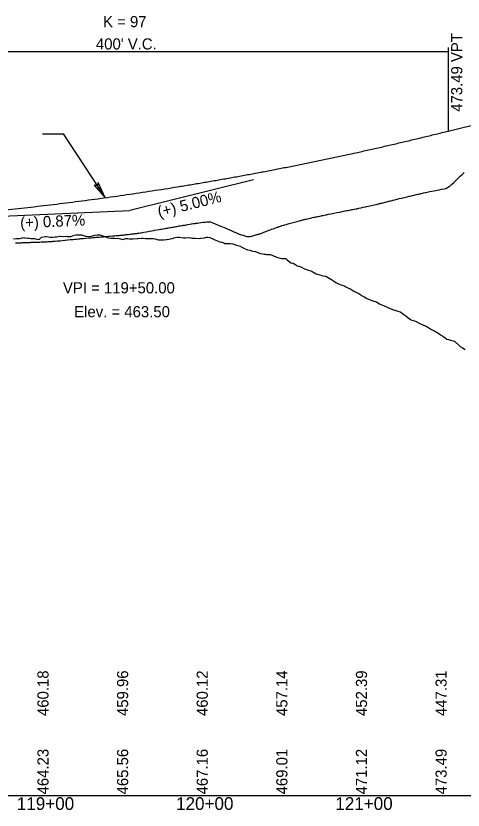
# Model space of a CAD drawing. Extents: x 2017200 to 2047700, y 854850 to 893350.
# Drawn here: x 2023378.5 to 2023659.3, y 862090.9 to 862589.8 of the extents above; entities that cross this region are included whole.
import ezdxf

# ---------------------------------------------------------------- set-up
doc = ezdxf.new("R2010")
doc.units = 0
for name, color, linetype in [('RD_DDB_GradeTX', 7, 'Continuous'), ('RD_DDB_Profile_Elev', 7, 'Continuous'), ('RD_DDB_Profile_EX', 7, 'Continuous'), ('RD_DDB_Profile_Lbl', 7, 'Continuous'), ('RD_DDB_Profile_PR', 7, 'Continuous'), ('RD_DDB_StaTX', 7, 'Continuous'), ('RD_DDB_StripGrade', 7, 'Continuous'), ('RD_DDB_VCLbl', 7, 'Continuous'), ('RD_GPK_Profile_Cell', 7, 'Continuous')]:
    doc.layers.add(name, color=color, linetype=linetype)

msp = doc.modelspace()

# ---------------------------------------------------------------- linework, layer by layer
at = {"layer": 'RD_DDB_GradeTX'}
for p in [(2023527.61, 862486.89), (2023370.08, 862464.03)]:
    msp.add_line(p, (2023450, 862467.5), dxfattribs=at)
at = {"layer": 'RD_DDB_Profile_Elev'}
msp.add_lwpolyline([(2023378.28, 862447.19), (2023378.98, 862447.22), (2023379.7, 862447.25), (2023380.47, 862447.28), (2023381.27, 862447.31), (2023381.93, 862447.33), (2023382.5, 862447.36), (2023383.29, 862447.39), (2023383.72, 862447.4), (2023384.48, 862447.43), (2023384.92, 862447.45), (2023385.5, 862447.47), (2023386.21, 862447.5), (2023386.92, 862447.52), (2023387.55, 862447.54), (2023388.07, 862447.57), (2023388.88, 862447.59), (2023389.28, 862447.61), (2023389.71, 862447.63), (2023390.57, 862447.66), (2023391.11, 862447.68), (2023392.03, 862447.71), (2023392.67, 862447.74), (2023393.6, 862447.77), (2023394.29, 862447.81), (2023395.18, 862447.84), (2023395.9, 862447.87), (2023396.94, 862447.91), (2023397.43, 862447.94), (2023398.13, 862447.97), (2023398.8, 862448), (2023399.34, 862448.03), (2023399.89, 862448.07), (2023400.56, 862448.11), (2023401.24, 862448.17), (2023401.75, 862448.2), (2023402.67, 862448.28), (2023403.07, 862448.31), (2023404.7, 862448.46), (2023405.89, 862448.58), (2023406.22, 862448.61), (2023407.85, 862448.78), (2023409.17, 862448.91), (2023409.51, 862448.94), (2023410.81, 862449.08), (2023411.12, 862449.11), (2023411.42, 862449.14), (2023412.57, 862449.26), (2023413.8, 862449.38), (2023414.56, 862449.45), (2023415.48, 862449.54), (2023416.59, 862449.64), (2023417.87, 862449.76), (2023418.66, 862449.84), (2023419.29, 862449.89), (2023420.46, 862450), (2023420.83, 862450.03), (2023422.42, 862450.18), (2023424, 862450.32), (2023425.46, 862450.45), (2023425.89, 862450.48), (2023426.8, 862450.56), (2023427.98, 862450.66), (2023428.72, 862450.72), (2023429.72, 862450.81), (2023430.71, 862450.89), (2023431.85, 862450.98), (2023432.18, 862451.01), (2023433.42, 862451.1), (2023433.78, 862451.13), (2023435.05, 862451.23), (2023435.44, 862451.26), (2023435.8, 862451.29), (2023436.75, 862451.37), (2023437.07, 862451.39), (2023437.39, 862451.42), (2023439.12, 862451.56), (2023440.58, 862451.68), (2023441.5, 862451.76), (2023441.98, 862451.8), (2023442.72, 862451.87), (2023443.29, 862451.92), (2023443.99, 862451.99), (2023444.32, 862452.03), (2023444.98, 862452.09), (2023445.6, 862452.17), (2023446.32, 862452.24), (2023447.03, 862452.33), (2023447.8, 862452.4), (2023448.54, 862452.49), (2023449.31, 862452.57), (2023450.05, 862452.66), (2023450.79, 862452.74), (2023451.48, 862452.83), (2023452.14, 862452.9), (2023452.76, 862452.98), (2023453.28, 862453.04), (2023453.85, 862453.12), (2023454.38, 862453.19), (2023454.85, 862453.27), (2023455.18, 862453.32), (2023455.6, 862453.38), (2023456.63, 862453.55), (2023457.17, 862453.63), (2023458.83, 862453.91), (2023460.44, 862454.19), (2023462.14, 862454.5), (2023463.85, 862454.79), (2023465.02, 862455), (2023465.7, 862455.12), (2023467.04, 862455.35), (2023468.17, 862455.55), (2023469.32, 862455.76), (2023469.96, 862455.87), (2023470.88, 862456.04), (2023471.25, 862456.1), (2023472.3, 862456.29), (2023472.94, 862456.4), (2023473.82, 862456.56), (2023474.29, 862456.64), (2023475.35, 862456.83), (2023475.8, 862456.9), (2023476.14, 862456.96), (2023476.56, 862457.03), (2023477.14, 862457.13), (2023477.5, 862457.2), (2023478.38, 862457.35), (2023478.9, 862457.44), (2023479.57, 862457.56), (2023480.31, 862457.69), (2023481.12, 862457.83), (2023481.72, 862457.93), (2023482.66, 862458.1), (2023483.1, 862458.17), (2023483.41, 862458.23), (2023483.8, 862458.29), (2023484.44, 862458.41), (2023484.75, 862458.45), (2023485.83, 862458.64), (2023486.2, 862458.7), (2023487.66, 862458.94), (2023488.65, 862459.11), (2023488.97, 862459.16), (2023489.8, 862459.3), (2023490.64, 862459.43), (2023491.03, 862459.49), (2023491.35, 862459.54), (2023492.45, 862459.69), (2023493.6, 862459.85), (2023494.9, 862460.02), (2023496.2, 862460.18), (2023497.37, 862460.33), (2023498.32, 862460.44), (2023500.77, 862460.35), (2023501.14, 862460.2), (2023502.09, 862459.81), (2023503.58, 862459.19), (2023505.07, 862458.57), (2023505.51, 862458.39), (2023506.61, 862457.93), (2023507.27, 862457.65), (2023508.2, 862457.27), (2023509.23, 862456.84), (2023509.85, 862456.58), (2023511.26, 862455.99), (2023511.57, 862455.86), (2023512.75, 862455.37), (2023513.62, 862455), (2023515.34, 862454.26), (2023516.63, 862453.7), (2023517.13, 862453.49), (2023518.02, 862453.1), (2023518.73, 862452.8), (2023519.58, 862452.46), (2023519.98, 862452.28), (2023521.17, 862452.06), (2023522.18, 862451.74), (2023522.74, 862451.42), (2023523.79, 862451.15), (2023524.82, 862451.13), (2023525.63, 862451.29), (2023526.14, 862451.41), (2023526.59, 862451.54), (2023527.27, 862451.72), (2023527.99, 862451.9), (2023528.54, 862452.06), (2023529.22, 862452.25), (2023529.78, 862452.41), (2023530.36, 862452.57), (2023530.84, 862452.73), (2023531.28, 862452.88), (2023531.72, 862453), (2023532.9, 862453.42), (2023534.14, 862453.9), (2023534.46, 862454.02), (2023535.8, 862454.53), (2023537.04, 862455), (2023537.42, 862455.14), (2023538.08, 862455.39), (2023539.3, 862455.84), (2023540.66, 862456.34), (2023541.03, 862456.48), (2023541.7, 862456.72), (2023542.1, 862456.87), (2023542.52, 862457.01), (2023542.89, 862457.13), (2023543.69, 862457.42), (2023544.12, 862457.55), (2023544.69, 862457.75), (2023545.34, 862457.94), (2023545.69, 862458.06), (2023546.58, 862458.32), (2023546.89, 862458.41), (2023547.25, 862458.51), (2023548.35, 862458.83), (2023548.94, 862459), (2023550.2, 862459.36), (2023551.78, 862459.8), (2023552.55, 862460.02), (2023553.41, 862460.26), (2023555.1, 862460.73), (2023556.47, 862461.11), (2023557.36, 862461.34), (2023557.69, 862461.42), (2023558.32, 862461.59), (2023558.9, 862461.73), (2023559.39, 862461.85), (2023559.79, 862461.94), (2023560.12, 862462.02), (2023560.77, 862462.17), (2023561.57, 862462.35), (2023562.38, 862462.53), (2023563.41, 862462.77), (2023564.11, 862462.92), (2023564.8, 862463.08), (2023565.86, 862463.31), (2023566.44, 862463.43), (2023567.03, 862463.56), (2023567.54, 862463.67), (2023567.98, 862463.77), (2023569.05, 862463.99), (2023569.36, 862464.06), (2023570.31, 862464.26), (2023570.65, 862464.34), (2023571.25, 862464.46), (2023572.15, 862464.65), (2023573.3, 862464.89), (2023573.8, 862465), (2023574.27, 862465.1), (2023574.76, 862465.2), (2023576.39, 862465.53), (2023578.2, 862465.9), (2023580.06, 862466.28), (2023581.72, 862466.61), (2023582.78, 862466.81), (2023583.32, 862466.92), (2023584.18, 862467.09), (2023585.12, 862467.27), (2023585.51, 862467.34), (2023586.28, 862467.49), (2023586.74, 862467.58), (2023587.17, 862467.66), (2023588.02, 862467.82), (2023588.74, 862467.96), (2023589.44, 862468.09), (2023589.98, 862468.2), (2023590.86, 862468.36), (2023591.38, 862468.46), (2023592.36, 862468.65), (2023592.81, 862468.74), (2023593.24, 862468.82), (2023593.91, 862468.97), (2023595.19, 862469.25), (2023595.98, 862469.43), (2023596.61, 862469.56), (2023598.15, 862469.92), (2023598.5, 862470), (2023599.89, 862470.31), (2023601.71, 862470.71), (2023603.38, 862471.08), (2023604.58, 862471.34), (2023604.97, 862471.44), (2023605.94, 862471.66), (2023606.48, 862471.8), (2023606.84, 862471.88), (2023607.22, 862471.96), (2023607.71, 862472.08), (2023608.43, 862472.26), (2023608.87, 862472.37), (2023609.75, 862472.6), (2023610.46, 862472.78), (2023610.8, 862472.87), (2023611.81, 862473.13), (2023612.31, 862473.26), (2023613.4, 862473.54), (2023614.07, 862473.72), (2023614.9, 862473.93), (2023615.21, 862474.01), (2023616.41, 862474.31), (2023617.18, 862474.5), (2023617.69, 862474.63), (2023618.11, 862474.73), (2023619.28, 862475.02), (2023620.79, 862475.4), (2023621.31, 862475.53), (2023622.49, 862475.81), (2023624.16, 862476.21), (2023624.93, 862476.4), (2023625.41, 862476.51), (2023625.85, 862476.61), (2023626.93, 862476.87), (2023627.53, 862477.01), (2023628.55, 862477.25), (2023629.18, 862477.39), (2023629.89, 862477.56), (2023630.79, 862477.76), (2023631.31, 862477.88), (2023632.32, 862478.11), (2023632.66, 862478.18), (2023633, 862478.25), (2023634.04, 862478.49), (2023634.44, 862478.57), (2023635.46, 862478.8), (2023635.84, 862478.88), (2023636.73, 862479.07), (2023637.7, 862479.28), (2023638.47, 862479.44), (2023639.73, 862479.71), (2023641.16, 862480), (2023643.03, 862480.37), (2023644.32, 862480.62), (2023645.81, 862480.91), (2023647.36, 862481.22), (2023648.38, 862481.41), (2023650.66, 862482.55), (2023651.02, 862482.89), (2023651.77, 862483.61), (2023652.08, 862483.89), (2023653.43, 862485.17), (2023653.88, 862485.61), (2023654.93, 862486.6), (2023655.75, 862487.39), (2023656.63, 862488.22), (2023657.5, 862489.06), (2023658.49, 862490), (2023660.06, 862491.51)], dxfattribs=at)
at = {"layer": 'RD_DDB_Profile_EX'}
msp.add_lwpolyline([(2023376.92, 862449.71), (2023378.85, 862450.02), (2023380.22, 862449.95), (2023381.03, 862450.06), (2023382.47, 862450.34), (2023382.82, 862450.41), (2023383.51, 862450.59), (2023384.07, 862450.5), (2023386.09, 862450.23), (2023386.8, 862450.14), (2023387.84, 862450.08), (2023389.71, 862449.97), (2023390.16, 862449.93), (2023392.38, 862449.44), (2023393.37, 862449.62), (2023394.66, 862450.73), (2023396.94, 862451.27), (2023397.58, 862451.19), (2023399.92, 862450.91), (2023400.56, 862450.84), (2023401.49, 862450.74), (2023403.2, 862451.01), (2023403.77, 862451.07), (2023404.18, 862451.12), (2023405.07, 862451.22), (2023406.05, 862451.36), (2023406.47, 862451.4), (2023407.8, 862451.33), (2023409.74, 862451.4), (2023410.61, 862451.3), (2023411.42, 862451.28), (2023413, 862451.27), (2023415.18, 862451.98), (2023416.27, 862452.34), (2023418.96, 862452.31), (2023419.76, 862452.3), (2023420.3, 862452.09), (2023422.28, 862451.4), (2023422.78, 862451.35), (2023424.59, 862451.31), (2023426.04, 862451.4), (2023428.04, 862451.97), (2023429.51, 862452.34), (2023431.22, 862452.18), (2023432.54, 862451.8), (2023433.13, 862451.57), (2023435.87, 862450.54), (2023436.75, 862450.43), (2023438.11, 862450.27), (2023439.03, 862450.18), (2023440.41, 862450.09), (2023442.27, 862449.96), (2023442.71, 862450.11), (2023443.99, 862449.75), (2023445.02, 862449.55), (2023445.51, 862449.44), (2023447.61, 862450.04), (2023448.75, 862449.95), (2023449.63, 862449.79), (2023451.23, 862449.78), (2023452.09, 862449.79), (2023454.85, 862449.92), (2023455.21, 862449.94), (2023457.46, 862450.12), (2023458.46, 862450.18), (2023459.93, 862450.08), (2023461.18, 862449.98), (2023461.67, 862450.01), (2023462.08, 862450.02), (2023462.8, 862450.03), (2023464.89, 862450), (2023465.7, 862449.77), (2023468.15, 862449.1), (2023469.32, 862449.09), (2023470.44, 862449.07), (2023471.33, 862449.23), (2023472.94, 862449.4), (2023473.34, 862449.44), (2023474.55, 862449.5), (2023476.56, 862450.03), (2023477.4, 862450.23), (2023477.76, 862450.36), (2023479.73, 862450.89), (2023480.18, 862450.88), (2023480.97, 862450.85), (2023483.8, 862450.5), (2023484.38, 862450.35), (2023484.92, 862450.46), (2023487.42, 862450.7), (2023489.04, 862450.28), (2023490.59, 862450.22), (2023491.03, 862450.2), (2023493.98, 862450.06), (2023494.65, 862450.16), (2023496.99, 862450.5), (2023498.27, 862450.72), (2023499.06, 862450.86), (2023500.19, 862450.54), (2023502.15, 862449.76), (2023503.05, 862449.3), (2023503.38, 862449.19), (2023505.51, 862448.32), (2023506.58, 862447.87), (2023507.74, 862447.67), (2023509.13, 862447.15), (2023509.77, 862446.92), (2023510.08, 862446.82), (2023510.96, 862446.87), (2023512.96, 862446.9), (2023514.78, 862446.53), (2023516.37, 862446.09), (2023517.12, 862445.73), (2023519.47, 862445.09), (2023519.98, 862444.82), (2023522.51, 862443.45), (2023523.6, 862443.01), (2023523.93, 862442.88), (2023525.69, 862442.57), (2023526.54, 862442.15), (2023527.22, 862442.03), (2023528.98, 862441.71), (2023530.84, 862440.94), (2023532.04, 862440.45), (2023533.65, 862440.27), (2023534.46, 862440.21), (2023535.21, 862440.15), (2023535.97, 862439.95), (2023538.48, 862439.91), (2023541.7, 862438.46), (2023543.07, 862438.07), (2023544.72, 862437.6), (2023545.44, 862437.46), (2023548.03, 862437.44), (2023548.94, 862436.63), (2023551.05, 862434.75), (2023552.55, 862434.48), (2023554.21, 862433.42), (2023554.93, 862432.91), (2023556.17, 862432.56), (2023557.36, 862432.24), (2023559.79, 862430.93), (2023560.52, 862430.67), (2023562.07, 862430.06), (2023563.68, 862429.64), (2023564.45, 862429.2), (2023567.03, 862427.88), (2023569.98, 862426.84), (2023570.65, 862426.71), (2023571.45, 862426.56), (2023573.13, 862426.27), (2023574.27, 862425.62), (2023576.27, 862424.48), (2023576.75, 862424.17), (2023577.89, 862423.43), (2023578.78, 862422.85), (2023579.42, 862422.4), (2023580.63, 862421.69), (2023581.5, 862421.35), (2023582.56, 862420.92), (2023583.57, 862420.63), (2023585.12, 862419.93), (2023585.7, 862419.67), (2023586.85, 862419.04), (2023588.37, 862418.37), (2023588.84, 862418.2), (2023590.78, 862416.98), (2023591.98, 862416.2), (2023592.36, 862416.09), (2023593.18, 862415.84), (2023595.12, 862414.54), (2023595.59, 862414.25), (2023595.98, 862414.01), (2023597.15, 862413.29), (2023598.25, 862412.69), (2023598.72, 862412.51), (2023599.6, 862412.11), (2023601.38, 862411.3), (2023603.22, 862410.67), (2023604.51, 862410.34), (2023605.23, 862409.95), (2023606.84, 862409.02), (2023607.68, 862408.54), (2023610.46, 862407.44), (2023610.77, 862407.32), (2023612.49, 862406.48), (2023614.07, 862405.77), (2023614.91, 862405.39), (2023617.01, 862404.8), (2023617.69, 862404.58), (2023618.44, 862404.35), (2023619.76, 862403.81), (2023620.14, 862403.7), (2023621.31, 862402.85), (2023622.19, 862402.22), (2023623.26, 862401.49), (2023624.62, 862400.37), (2023624.93, 862400.14), (2023626.37, 862399.06), (2023627.05, 862398.6), (2023628.55, 862398.29), (2023629.51, 862398.09), (2023632.17, 862396.66), (2023632.61, 862396.43), (2023634.36, 862395.63), (2023635.79, 862395.05), (2023636.79, 862394.39), (2023638.83, 862393.19), (2023639.41, 862392.87), (2023640.73, 862392.13), (2023641.94, 862391.49), (2023643.03, 862390.94), (2023644.13, 862390.39), (2023645.05, 862389.42), (2023646.65, 862388.59), (2023648.15, 862387.52), (2023649.03, 862386.79), (2023650.26, 862386.46), (2023651.48, 862386.07), (2023652.31, 862385.86), (2023653.93, 862385.44), (2023654.36, 862385.09), (2023656.39, 862383.15), (2023657.5, 862382.12), (2023658.85, 862381.36), (2023660.57, 862380.35)], dxfattribs=at)
at = {"layer": 'RD_DDB_Profile_Lbl'}
msp.add_lwpolyline([(2023395.22, 862515.8), (2023408.08, 862515.8), (2023434.53, 862475.62)], dxfattribs=at)
msp.add_lwpolyline([(2023434.53, 862475.62), (2023430.07, 862485.12), (2023429.7, 862482.96), (2023427.57, 862483.47)], close=True, dxfattribs=at)
at = {"layer": 'RD_DDB_Profile_PR'}
msp.add_line((2023650, 862517.47), (2023732.77, 862538.15), dxfattribs=at)
msp.add_spline([(2023250, 862458.83), (2023258, 862459.19), (2023266, 862459.59), (2023274, 862460.02), (2023282, 862460.48), (2023290, 862460.97), (2023298, 862461.5), (2023306, 862462.07), (2023314, 862462.66), (2023322, 862463.29), (2023330, 862463.95), (2023338, 862464.64), (2023346, 862465.37), (2023354, 862466.13), (2023362, 862466.92), (2023370, 862467.75), (2023378, 862468.61), (2023386, 862469.5), (2023394, 862470.42), (2023402, 862471.38), (2023410, 862472.37), (2023418, 862473.4), (2023426, 862474.45), (2023434, 862475.54), (2023442, 862476.67), (2023450, 862477.82), (2023458, 862479.01), (2023466, 862480.24), (2023474, 862481.49), (2023482, 862482.78), (2023490, 862484.1), (2023498, 862485.46), (2023506, 862486.84), (2023514, 862488.26), (2023522, 862489.72), (2023530, 862491.2), (2023538, 862492.72), (2023546, 862494.28), (2023554, 862495.86), (2023562, 862497.48), (2023570, 862499.13), (2023578, 862500.82), (2023586, 862502.54), (2023594, 862504.29), (2023602, 862506.07), (2023610, 862507.89), (2023618, 862509.74), (2023626, 862511.62), (2023634, 862513.54), (2023642, 862515.49), (2023650, 862517.47)], degree=3, dxfattribs=at)
at = {"layer": 'RD_DDB_VCLbl'}
for p, q in [((2023650, 862569.97), (2023650, 862517.47)), ((2023250, 862567.47), (2023650, 862567.47))]:
    msp.add_line(p, q, dxfattribs=at)
at = {"layer": 'RD_GPK_Profile_Cell'}
msp.add_line((2020500, 862100), (2024800, 862100), dxfattribs=at)

# ---------------------------------------------------------------- texts
at = {"layer": 'RD_DDB_GradeTX'}
for s, rotation, p in [('(+) 5.00%', 14.0281, (2023468.47, 862463.22)), ('(+) 0.87%', 2.483, (2023381.33, 862456.4))]:
    msp.add_text(s, height=7, rotation=rotation, dxfattribs=at).set_placement(p)
at = {"layer": 'RD_DDB_Profile_Lbl'}
for s, p in [('VPI = 119+50.00', (2023408.04, 862415.5)), ('Elev. = 463.50', (2023415.11, 862400.5))]:
    msp.add_text(s, height=7, dxfattribs=at).set_placement(p)
at = {"layer": 'RD_DDB_StaTX'}
for s, p in [('119+00', (2023379.1, 862091)), ('120+00', (2023479.1, 862091)), ('121+00', (2023579.1, 862091))]:
    msp.add_text(s, height=8, dxfattribs=at).set_placement(p)
at = {"layer": 'RD_DDB_StripGrade'}
for s, p in [('473.49 VPT', (2023658.82, 862529.57)), ('460.18', (2023399, 862150)), ('459.96', (2023449, 862150)), ('460.12', (2023499, 862150)), ('457.14', (2023549, 862150)), ('452.39', (2023599, 862150)), ('447.31', (2023649, 862150)), ('464.23', (2023399, 862100.75)), ('465.56', (2023449, 862100.75)), ('467.16', (2023499, 862100.75)), ('469.01', (2023549, 862100.75)), ('471.12', (2023599, 862100.75)), ('473.49', (2023649, 862100.75))]:
    msp.add_text(s, height=7, rotation=90, dxfattribs=at).set_placement(p)
at = {"layer": 'RD_DDB_VCLbl'}
for s, p in [('K = 97', (2023433.22, 862582.72)), ("400' V.C.", (2023428.75, 862568.72))]:
    msp.add_text(s, height=7, dxfattribs=at).set_placement(p)

doc.saveas('drawing.dxf')
